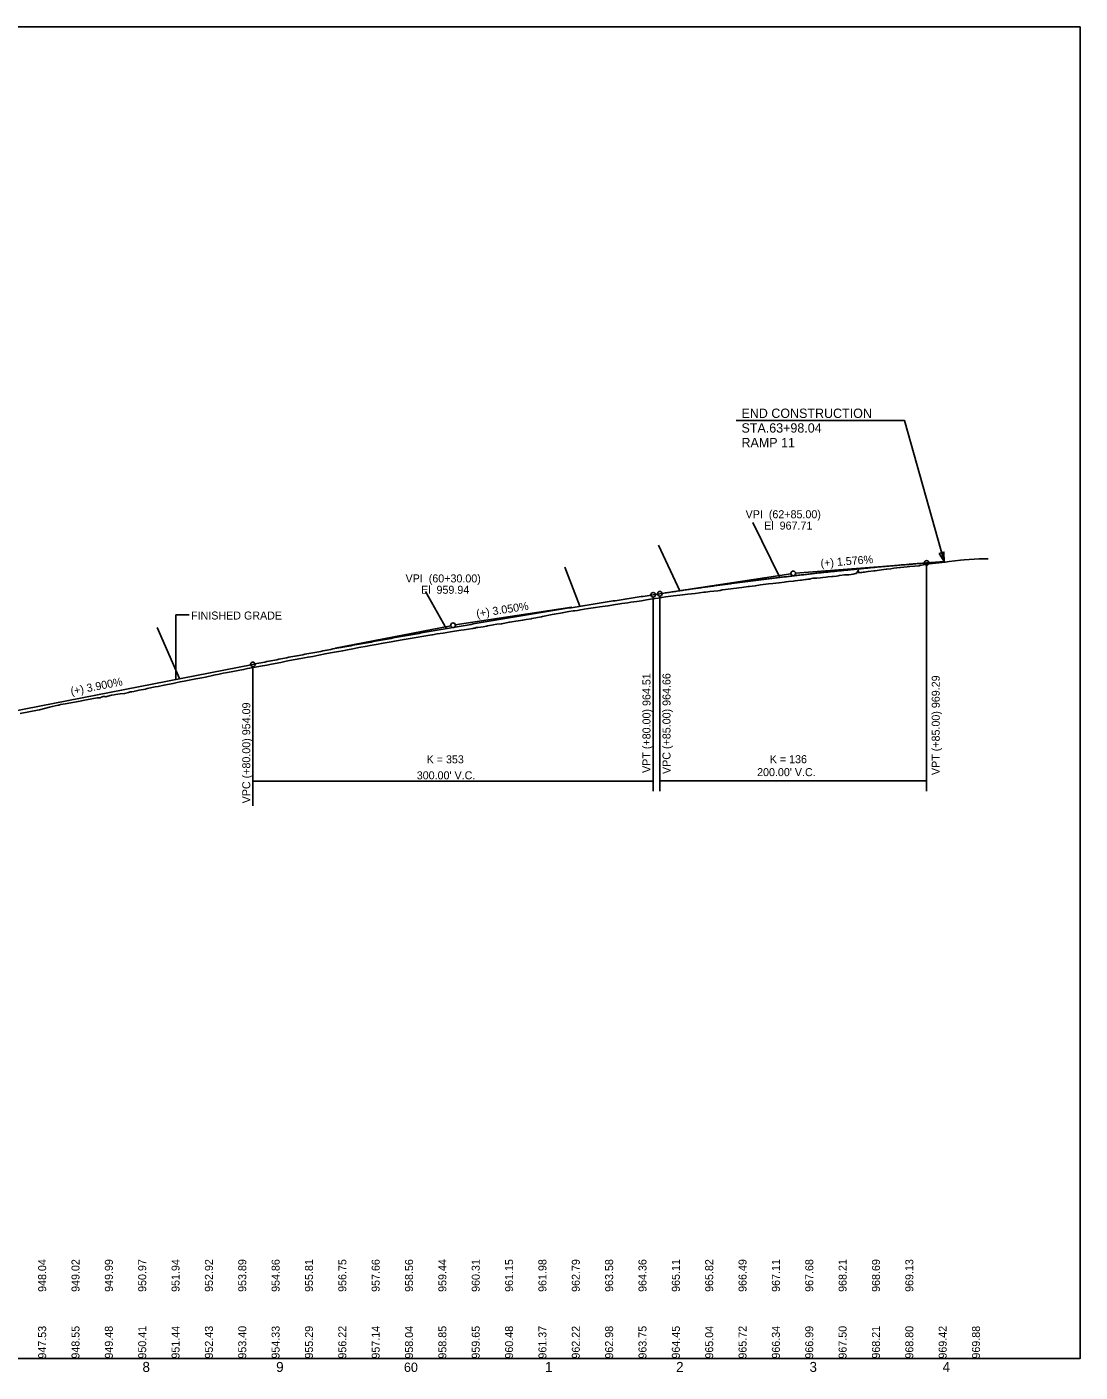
# Model space of a CAD drawing. Extents: x 126 to 16974612, y 7 to 12550779.
# Drawn here: x 16973823 to 16974612, y 12549769 to 12550777 of the extents above; entities that cross this region are included whole.
import ezdxf

# ---------------------------------------------------------------- set-up
doc = ezdxf.new("R2010")
doc.units = 0
for name, color, linetype in [('ANNOT_CONTOUR', 7, 'Continuous'), ('CLS_P_Shld_Gore', 7, 'Continuous'), ('CLS_Shear_Line', 7, 'Continuous'), ('Default', 7, 'Continuous'), ('RD_EX_Conc-ZZ', 7, 'Continuous'), ('RD_HC_CL_50', 7, 'Continuous'), ('RD_HC_Data', 7, 'Continuous'), ('RD_HC_Data_Tic', 7, 'Continuous'), ('RD_HC_Points', 7, 'Continuous'), ('RD_PD_ConcMed', 7, 'Continuous'), ('RD_PD_SuperShp1', 7, 'Continuous'), ('RD_Sketch1', 7, 'Continuous'), ('RD_TX_Utilities', 7, 'Continuous')]:
    doc.layers.add(name, color=color, linetype=linetype)

msp = doc.modelspace()

# ---------------------------------------------------------------- linework, layer by layer
at = {"layer": 'CLS_P_Shld_Gore'}
for p, q in [((16973944.4, 12550336.2), (16973934.4, 12550336.2)), ((16973934.4, 12550336.2), (16973934.4, 12550287.9))]:
    msp.add_line(p, q, dxfattribs=at)
at = {"layer": 'CLS_Shear_Line'}
for p, q in [((16974497.2, 12550204.2), (16974497.2, 12550373.5)), ((16974292.2, 12550204.2), (16974292.2, 12550349.6)), ((16974297.2, 12550204.2), (16974297.2, 12550350.4)), ((16973992.2, 12550193.2), (16973992.2, 12550297.5)), ((16973992.2, 12550211.7), (16974292.2, 12550211.7)), ((16974297.2, 12550212), (16974497.2, 12550212))]:
    msp.add_line(p, q, dxfattribs=at)
for centre in [(16974497.2, 12550375.2), (16974292.2, 12550351.3), (16974297.2, 12550352.1), (16973992.2, 12550299.2)]:
    msp.add_circle(centre, 1.75, dxfattribs=at)
at = {"layer": 'Default'}
msp.add_lwpolyline([(16973112.2, 12549778.8), (16974612.2, 12549778.8), (16974612.2, 12550777), (16973112.2, 12550777)], close=True, dxfattribs=at)
at = {"layer": 'RD_EX_Conc-ZZ'}
for p, q in [((16974486.9, 12550374.4), (16974399, 12550367.5)), ((16974308.2, 12550353.8), (16974395.5, 12550367.1)), ((16974231.2, 12550342), (16974143.9, 12550328.7)), ((16974053.9, 12550311.2), (16974140.5, 12550328.1))]:
    msp.add_line(p, q, dxfattribs=at)
for centre in [(16974397.2, 12550367.4), (16974142.2, 12550328.5)]:
    msp.add_circle(centre, 1.75, dxfattribs=at)
at = {"layer": 'RD_HC_Data'}
msp.add_line((16973112.2, 12549778.8), (16974543.3, 12549778.8), dxfattribs=at)
at = {"layer": 'RD_HC_Points'}
for points in [[(16974442.2, 12550366.7), (16974443.8, 12550367.2), (16974444.6, 12550367.4), (16974445.1, 12550368.4), (16974445.9, 12550369.6), (16974446.3, 12550368.1), (16974446.3, 12550367.9), (16974447.8, 12550368), (16974448.6, 12550368.1), (16974449.7, 12550368.2), (16974450.5, 12550368.3), (16974453.1, 12550368.7), (16974453.4, 12550368.7), (16974457.6, 12550369.2), (16974458.6, 12550369.3), (16974461.7, 12550369.8), (16974463.4, 12550370), (16974466.8, 12550370.5), (16974467.3, 12550370.5), (16974470.3, 12550370.8), (16974472.7, 12550371.2), (16974477.1, 12550371.7), (16974477.7, 12550371.8), (16974482.6, 12550372.4), (16974483.7, 12550372.5), (16974484.6, 12550372.6), (16974491.6, 12550373.1), (16974492, 12550373.2), (16974494.8, 12550373.9), (16974496.9, 12550374.2), (16974511, 12550375.7), (16974514, 12550376.2), (16974522.6, 12550377.2), (16974525.4, 12550377.5), (16974536.6, 12550378.2), (16974537.9, 12550378.2), (16974543.3, 12550378.2)], [(16974178.3, 12550329.6), (16974178.8, 12550329.6), (16974184.3, 12550330.8), (16974184.7, 12550330.8), (16974187.7, 12550331.3), (16974189.2, 12550331.5), (16974194.5, 12550332.4), (16974195.7, 12550332.5), (16974197, 12550332.7), (16974200.7, 12550333.4), (16974201.2, 12550333.5), (16974208.6, 12550334.9), (16974209.3, 12550335.1), (16974216.5, 12550336.5), (16974218.1, 12550336.7), (16974224.2, 12550337.9), (16974225.2, 12550338), (16974227.8, 12550338.5), (16974229.1, 12550338.7), (16974232.2, 12550339.2), (16974233.4, 12550339.3), (16974235.4, 12550339.6), (16974236.6, 12550339.8), (16974240.5, 12550340.5), (16974243.7, 12550341), (16974248.9, 12550341.8), (16974252.3, 12550342.3), (16974258.1, 12550343.1), (16974258.5, 12550343.1), (16974262.4, 12550343.7), (16974267.1, 12550344.5), (16974268.7, 12550344.7), (16974273.3, 12550345.4), (16974275.4, 12550345.8), (16974279.9, 12550346.4), (16974283.5, 12550346.9), (16974287.3, 12550347.6), (16974291.6, 12550348.2), (16974295.9, 12550348.9), (16974301.5, 12550349.8), (16974307.4, 12550350.5), (16974312.3, 12550351.1), (16974318.1, 12550351.8), (16974323.7, 12550352.4), (16974330.3, 12550353.2), (16974331.4, 12550353.4), (16974333.1, 12550353.6), (16974334.7, 12550353.8), (16974337.7, 12550354), (16974340.6, 12550354.4), (16974342.4, 12550354.6), (16974343.9, 12550355), (16974346.4, 12550355.2), (16974352.4, 12550356), (16974354.6, 12550356.3), (16974356.3, 12550356.5), (16974358.6, 12550356.8), (16974363.5, 12550357.6), (16974364.5, 12550357.6), (16974366.5, 12550357.8), (16974368.7, 12550358), (16974372.7, 12550358.7), (16974374.7, 12550359), (16974378.6, 12550359.5), (16974381.9, 12550359.8), (16974386.3, 12550360.4), (16974386.7, 12550360.4), (16974390.4, 12550360.8), (16974391.8, 12550361.1), (16974392, 12550361.1), (16974393.7, 12550361.2), (16974397.1, 12550361.6), (16974397.5, 12550361.6), (16974398.6, 12550361.8), (16974402.7, 12550362.2), (16974403.4, 12550362.3), (16974406.3, 12550362.7), (16974407.1, 12550362.8), (16974408.2, 12550363), (16974409.3, 12550363.1), (16974409.9, 12550363.1), (16974410, 12550363.2), (16974411.9, 12550363.7), (16974412.9, 12550363.9), (16974413.4, 12550363.9), (16974413.7, 12550363.9), (16974415, 12550363.9), (16974417.6, 12550364), (16974419.5, 12550364.2), (16974421.9, 12550364.5), (16974423.2, 12550364.7), (16974426, 12550365), (16974427.2, 12550365.1), (16974429.5, 12550365.3), (16974430.9, 12550365.5), (16974431.8, 12550365.8), (16974435.6, 12550366.2), (16974437.8, 12550366.3), (16974438.9, 12550366.4), (16974440.5, 12550366.6), (16974442.2, 12550366.7)], [(16973832.2, 12550265.2), (16973839.8, 12550267.1), (16973841.8, 12550267.5), (16973846.3, 12550268.6), (16973846.6, 12550268.7), (16973847.9, 12550269), (16973851.5, 12550269.7), (16973855.8, 12550270.4), (16973858.5, 12550270.9), (16973862.7, 12550271.6), (16973865.9, 12550272.3), (16973867.4, 12550272.5), (16973875.4, 12550274), (16973876.3, 12550274.2), (16973877.7, 12550274), (16973878, 12550274.2), (16973878.4, 12550274.6), (16973879.3, 12550274.8), (16973880, 12550275), (16973880.3, 12550275.1), (16973881.2, 12550275.1), (16973881.6, 12550274.9), (16973886.2, 12550276), (16973888.2, 12550276.4), (16973889.3, 12550276.5), (16973892.6, 12550277), (16973896, 12550277.3), (16973899, 12550278), (16973900.4, 12550278.5), (16973901.3, 12550278.6), (16973903, 12550278.9), (16973903.8, 12550279.2), (16973906.8, 12550279.9), (16973911.6, 12550280.7), (16973913, 12550281), (16973918.9, 12550282.3), (16973921.1, 12550282.6), (16973925.5, 12550283.5), (16973932.3, 12550284.9), (16973935.3, 12550285.5), (16973937.6, 12550286.1), (16973940.7, 12550286.6), (16973949.5, 12550288.3), (16973953.8, 12550289.1), (16973956.7, 12550289.7), (16973962.8, 12550291.1), (16973966.8, 12550291.8), (16973969.9, 12550292.5), (16973973.1, 12550293), (16973985.2, 12550295.3), (16973988.1, 12550296), (16973989.7, 12550296.3), (16973991.1, 12550296.6), (16973997.9, 12550297.8), (16974002.5, 12550298.6), (16974006, 12550299.3), (16974013.1, 12550300.6), (16974017.2, 12550301.5), (16974019.7, 12550302), (16974028, 12550303.5), (16974033.5, 12550304.6), (16974037.2, 12550305.2), (16974041.7, 12550306.1), (16974046.3, 12550307.1), (16974050.3, 12550307.8), (16974056.4, 12550308.8), (16974059.5, 12550309.4), (16974061.8, 12550309.8), (16974068.4, 12550311.1), (16974071.5, 12550311.7), (16974077.7, 12550312.8), (16974080, 12550313.2), (16974086.1, 12550314.3), (16974088.4, 12550314.7), (16974095.9, 12550316.1), (16974098.4, 12550316.5), (16974105.5, 12550317.9), (16974108.5, 12550318.4), (16974116, 12550319.6), (16974118.8, 12550320.1), (16974126.4, 12550321.4), (16974126.8, 12550321.4), (16974130.3, 12550322), (16974134.7, 12550322.6), (16974140.2, 12550323.5), (16974140.2, 12550323.5), (16974148, 12550324.7), (16974150.6, 12550325.1), (16974157, 12550326), (16974157.9, 12550326.2), (16974158.8, 12550326.4), (16974159.5, 12550326.7), (16974160.7, 12550326.9), (16974164.7, 12550327.3), (16974167.2, 12550327.9), (16974167.9, 12550328), (16974168.1, 12550328.1), (16974171, 12550328.5), (16974172.3, 12550328.8), (16974175, 12550329.2), (16974178.3, 12550329.6)], [(16973817.8, 12550262.4), (16973830.7, 12550264.8), (16973832.2, 12550265.2)]]:
    msp.add_lwpolyline(points, dxfattribs=at)
at = {"layer": 'RD_PD_ConcMed'}
for p, q in [((16974497.2, 12550375.2), (16974510.3, 12550376.3)), ((16974292.2, 12550351.3), (16974297.2, 12550352.1)), ((16973767.2, 12550255.3), (16973992.2, 12550299.2))]:
    msp.add_line(p, q, dxfattribs=at)
for points in [[(16974297.2, 12550352.1), (16974301.2, 12550352.7), (16974305.2, 12550353.3), (16974309.2, 12550353.9), (16974313.2, 12550354.5), (16974317.2, 12550355.1), (16974321.2, 12550355.7), (16974325.2, 12550356.2), (16974329.2, 12550356.8), (16974333.2, 12550357.4), (16974337.2, 12550357.9), (16974341.2, 12550358.5), (16974345.2, 12550359), (16974349.2, 12550359.5), (16974353.2, 12550360.1), (16974357.2, 12550360.6), (16974361.2, 12550361.1), (16974365.2, 12550361.6), (16974369.2, 12550362.1), (16974373.2, 12550362.6), (16974377.2, 12550363.1), (16974381.2, 12550363.6), (16974385.2, 12550364.1), (16974389.2, 12550364.6), (16974393.2, 12550365), (16974397.2, 12550365.5), (16974401.2, 12550366), (16974405.2, 12550366.4), (16974409.2, 12550366.9), (16974413.2, 12550367.3), (16974417.2, 12550367.8), (16974421.2, 12550368.2), (16974425.2, 12550368.6), (16974429.2, 12550369), (16974433.2, 12550369.4), (16974437.2, 12550369.8), (16974441.2, 12550370.2), (16974445.2, 12550370.6), (16974449.2, 12550371), (16974453.2, 12550371.4), (16974457.2, 12550371.8), (16974461.2, 12550372.2), (16974465.2, 12550372.5), (16974469.2, 12550372.9), (16974473.2, 12550373.2), (16974477.2, 12550373.6), (16974481.2, 12550373.9), (16974485.2, 12550374.3), (16974489.2, 12550374.6), (16974493.2, 12550374.9), (16974497.2, 12550375.2)], [(16973992.2, 12550299.2), (16973998.2, 12550300.4), (16974004.2, 12550301.5), (16974010.2, 12550302.7), (16974016.2, 12550303.9), (16974022.2, 12550305), (16974028.2, 12550306.1), (16974034.2, 12550307.3), (16974040.2, 12550308.4), (16974046.2, 12550309.5), (16974052.2, 12550310.7), (16974058.2, 12550311.8), (16974064.2, 12550312.9), (16974070.2, 12550314), (16974076.2, 12550315.1), (16974082.2, 12550316.2), (16974088.2, 12550317.3), (16974094.2, 12550318.4), (16974100.2, 12550319.5), (16974106.2, 12550320.5), (16974112.2, 12550321.6), (16974118.2, 12550322.7), (16974124.2, 12550323.7), (16974130.2, 12550324.8), (16974136.2, 12550325.8), (16974142.2, 12550326.9), (16974148.2, 12550327.9), (16974154.2, 12550328.9), (16974160.2, 12550330), (16974166.2, 12550331), (16974172.2, 12550332), (16974178.2, 12550333), (16974184.2, 12550334), (16974190.2, 12550335.1), (16974196.2, 12550336.1), (16974202.2, 12550337), (16974208.2, 12550338), (16974214.2, 12550339), (16974220.2, 12550340), (16974226.2, 12550341), (16974232.2, 12550341.9), (16974238.2, 12550342.9), (16974244.2, 12550343.9), (16974250.2, 12550344.8), (16974256.2, 12550345.8), (16974262.2, 12550346.7), (16974268.2, 12550347.6), (16974274.2, 12550348.6), (16974280.2, 12550349.5), (16974286.2, 12550350.4), (16974292.2, 12550351.3)]]:
    msp.add_spline(points, degree=3, dxfattribs=at)
at = {"layer": 'RD_Sketch1'}
for p, q in [((16974387.2, 12550364.3), (16974366.9, 12550405.4)), ((16974312.2, 12550354.3), (16974296.2, 12550388.6)), ((16974237.2, 12550342.9), (16974225.9, 12550372)), ((16974137.2, 12550325.8), (16974121.5, 12550353.9)), ((16973937.2, 12550288.5), (16973920.4, 12550326.8))]:
    msp.add_line(p, q, dxfattribs=at)
at = {"layer": 'RD_TX_Utilities'}
msp.add_line((16974471, 12550481.9), (16974354.4, 12550481.9), dxfattribs=at)
msp.add_lwpolyline([(16974471, 12550481.9), (16974480.7, 12550481.9), (16974510.3, 12550376.3)], dxfattribs=at)
msp.add_lwpolyline([(16974506.7, 12550382.3), (16974510.3, 12550376.3), (16974510.2, 12550383.3)], close=True, dxfattribs=at)

# ---------------------------------------------------------------- texts
at = {"layer": 'ANNOT_CONTOUR'}
for s, p in [('947.53', (16973837.2, 12549778.8)), ('948.55', (16973862.2, 12549778.8)), ('949.48', (16973887.2, 12549778.8)), ('950.41', (16973912.2, 12549778.8)), ('951.44', (16973937.2, 12549778.8)), ('952.43', (16973962.2, 12549778.8)), ('953.40', (16973987.2, 12549778.8)), ('954.33', (16974012.2, 12549778.8)), ('955.29', (16974037.2, 12549778.8)), ('956.22', (16974062.2, 12549778.8)), ('957.14', (16974087.2, 12549778.8)), ('958.04', (16974112.2, 12549778.8)), ('958.85', (16974137.2, 12549778.8)), ('959.65', (16974162.2, 12549778.8)), ('960.48', (16974187.2, 12549778.8)), ('961.37', (16974212.2, 12549778.8)), ('962.22', (16974237.2, 12549778.8)), ('962.98', (16974262.2, 12549778.8)), ('963.75', (16974287.2, 12549778.8)), ('964.45', (16974312.2, 12549778.8)), ('965.04', (16974337.2, 12549778.8)), ('965.72', (16974362.2, 12549778.8)), ('966.34', (16974387.2, 12549778.8)), ('966.99', (16974412.2, 12549778.8)), ('967.50', (16974437.2, 12549778.8)), ('968.21', (16974462.2, 12549778.8)), ('968.80', (16974487.2, 12549778.8)), ('969.42', (16974512.2, 12549778.8)), ('969.88', (16974537.2, 12549778.8))]:
    msp.add_text(s, height=6, rotation=90, dxfattribs=at).set_placement(p)
at = {"layer": 'CLS_P_Shld_Gore'}
msp.add_text('FINISHED GRADE', height=6, dxfattribs=at).set_placement((16973945.8, 12550332.8))
at = {"layer": 'CLS_Shear_Line'}
for s, p in [('VPT (+80.00) 964.51', (16974290.2, 12550217.8)), ('VPC (+85.00) 964.66', (16974305.2, 12550217)), ('VPT (+85.00) 969.29', (16974507, 12550216.2)), ('VPC (+80.00) 954.09', (16973990.2, 12550195))]:
    msp.add_text(s, height=6, rotation=90, dxfattribs=at).set_placement(p)
for s, p in [('K = 353', (16974122.4, 12550225)), ('K = 136', (16974379.6, 12550225.1)), ("300.00' V.C.", (16974115, 12550213)), ("200.00' V.C.", (16974370.1, 12550215.4))]:
    msp.add_text(s, height=6, dxfattribs=at).set_placement(p)
at = {"layer": 'RD_EX_Conc-ZZ'}
for s, p in [('VPI  (62+85.00)', (16974361.5, 12550408.7)), ('El  967.71', (16974375.4, 12550400.2)), ('VPI  (60+30.00)', (16974106.6, 12550360.6)), ('El  959.94', (16974118.2, 12550352.1))]:
    msp.add_text(s, height=6, dxfattribs=at).set_placement(p)
at = {"layer": 'RD_HC_CL_50'}
for s, p in [('948.04', (16973837.2, 12549828.8)), ('949.02', (16973862.2, 12549828.8)), ('949.99', (16973887.2, 12549828.8)), ('950.97', (16973912.2, 12549828.8)), ('951.94', (16973937.2, 12549828.8)), ('952.92', (16973962.2, 12549828.8)), ('953.89', (16973987.2, 12549828.8)), ('954.86', (16974012.2, 12549828.8)), ('955.81', (16974037.2, 12549828.8)), ('956.75', (16974062.2, 12549828.8)), ('957.66', (16974087.2, 12549828.8)), ('958.56', (16974112.2, 12549828.8)), ('959.44', (16974137.2, 12549828.8)), ('960.31', (16974162.2, 12549828.8)), ('961.15', (16974187.2, 12549828.8)), ('961.98', (16974212.2, 12549828.8)), ('962.79', (16974237.2, 12549828.8)), ('963.58', (16974262.2, 12549828.8)), ('964.36', (16974287.2, 12549828.8)), ('965.11', (16974312.2, 12549828.8)), ('965.82', (16974337.2, 12549828.8)), ('966.49', (16974362.2, 12549828.8)), ('967.11', (16974387.2, 12549828.8)), ('967.68', (16974412.2, 12549828.8)), ('968.21', (16974437.2, 12549828.8)), ('968.69', (16974462.2, 12549828.8)), ('969.13', (16974487.2, 12549828.8))]:
    msp.add_text(s, height=6, rotation=90, dxfattribs=at).set_placement(p)
at = {"layer": 'RD_HC_Data_Tic'}
for s, height, p in [('8', 7.5, (16973909.4, 12549768.8)), ('9', 7.5, (16974009.6, 12549768.8)), ('60', 7, (16974105.4, 12549768.8)), ('1', 7.5, (16974211.2, 12549768.8)), ('2', 7.5, (16974309.4, 12549768.8)), ('3', 7.5, (16974409.4, 12549768.8)), ('4', 7.5, (16974509.2, 12549768.8))]:
    msp.add_text(s, height=height, dxfattribs=at).set_placement(p)
at = {"layer": 'RD_PD_SuperShp1'}
for s, rotation, p in [('(+) 1.576%', 4.5045, (16974417.9, 12550372)), ('(+) 3.050%', 8.6708, (16974160.1, 12550334.2)), ('(+) 3.900%', 11.0342, (16973856.1, 12550276))]:
    msp.add_text(s, height=6, rotation=rotation, dxfattribs=at).set_placement(p)
at = {"layer": 'RD_TX_Utilities'}
for s, p in [('END CONSTRUCTION', (16974358.4, 12550483.9)), ('STA.63+98.04', (16974358.4, 12550472.9)), ('RAMP 11', (16974358.4, 12550461.9))]:
    msp.add_text(s, height=7, dxfattribs=at).set_placement(p)

doc.saveas('drawing.dxf')
